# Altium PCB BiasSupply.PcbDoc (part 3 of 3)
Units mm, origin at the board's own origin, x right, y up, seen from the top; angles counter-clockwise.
Board outline 39 x 40.5 mm, 4 copper layers (Top Layer, Layer 2, Layer3, Bottom Layer), stack 0.661 mm thick; 168 components, 80 nets, 408 pads, 115 vias.
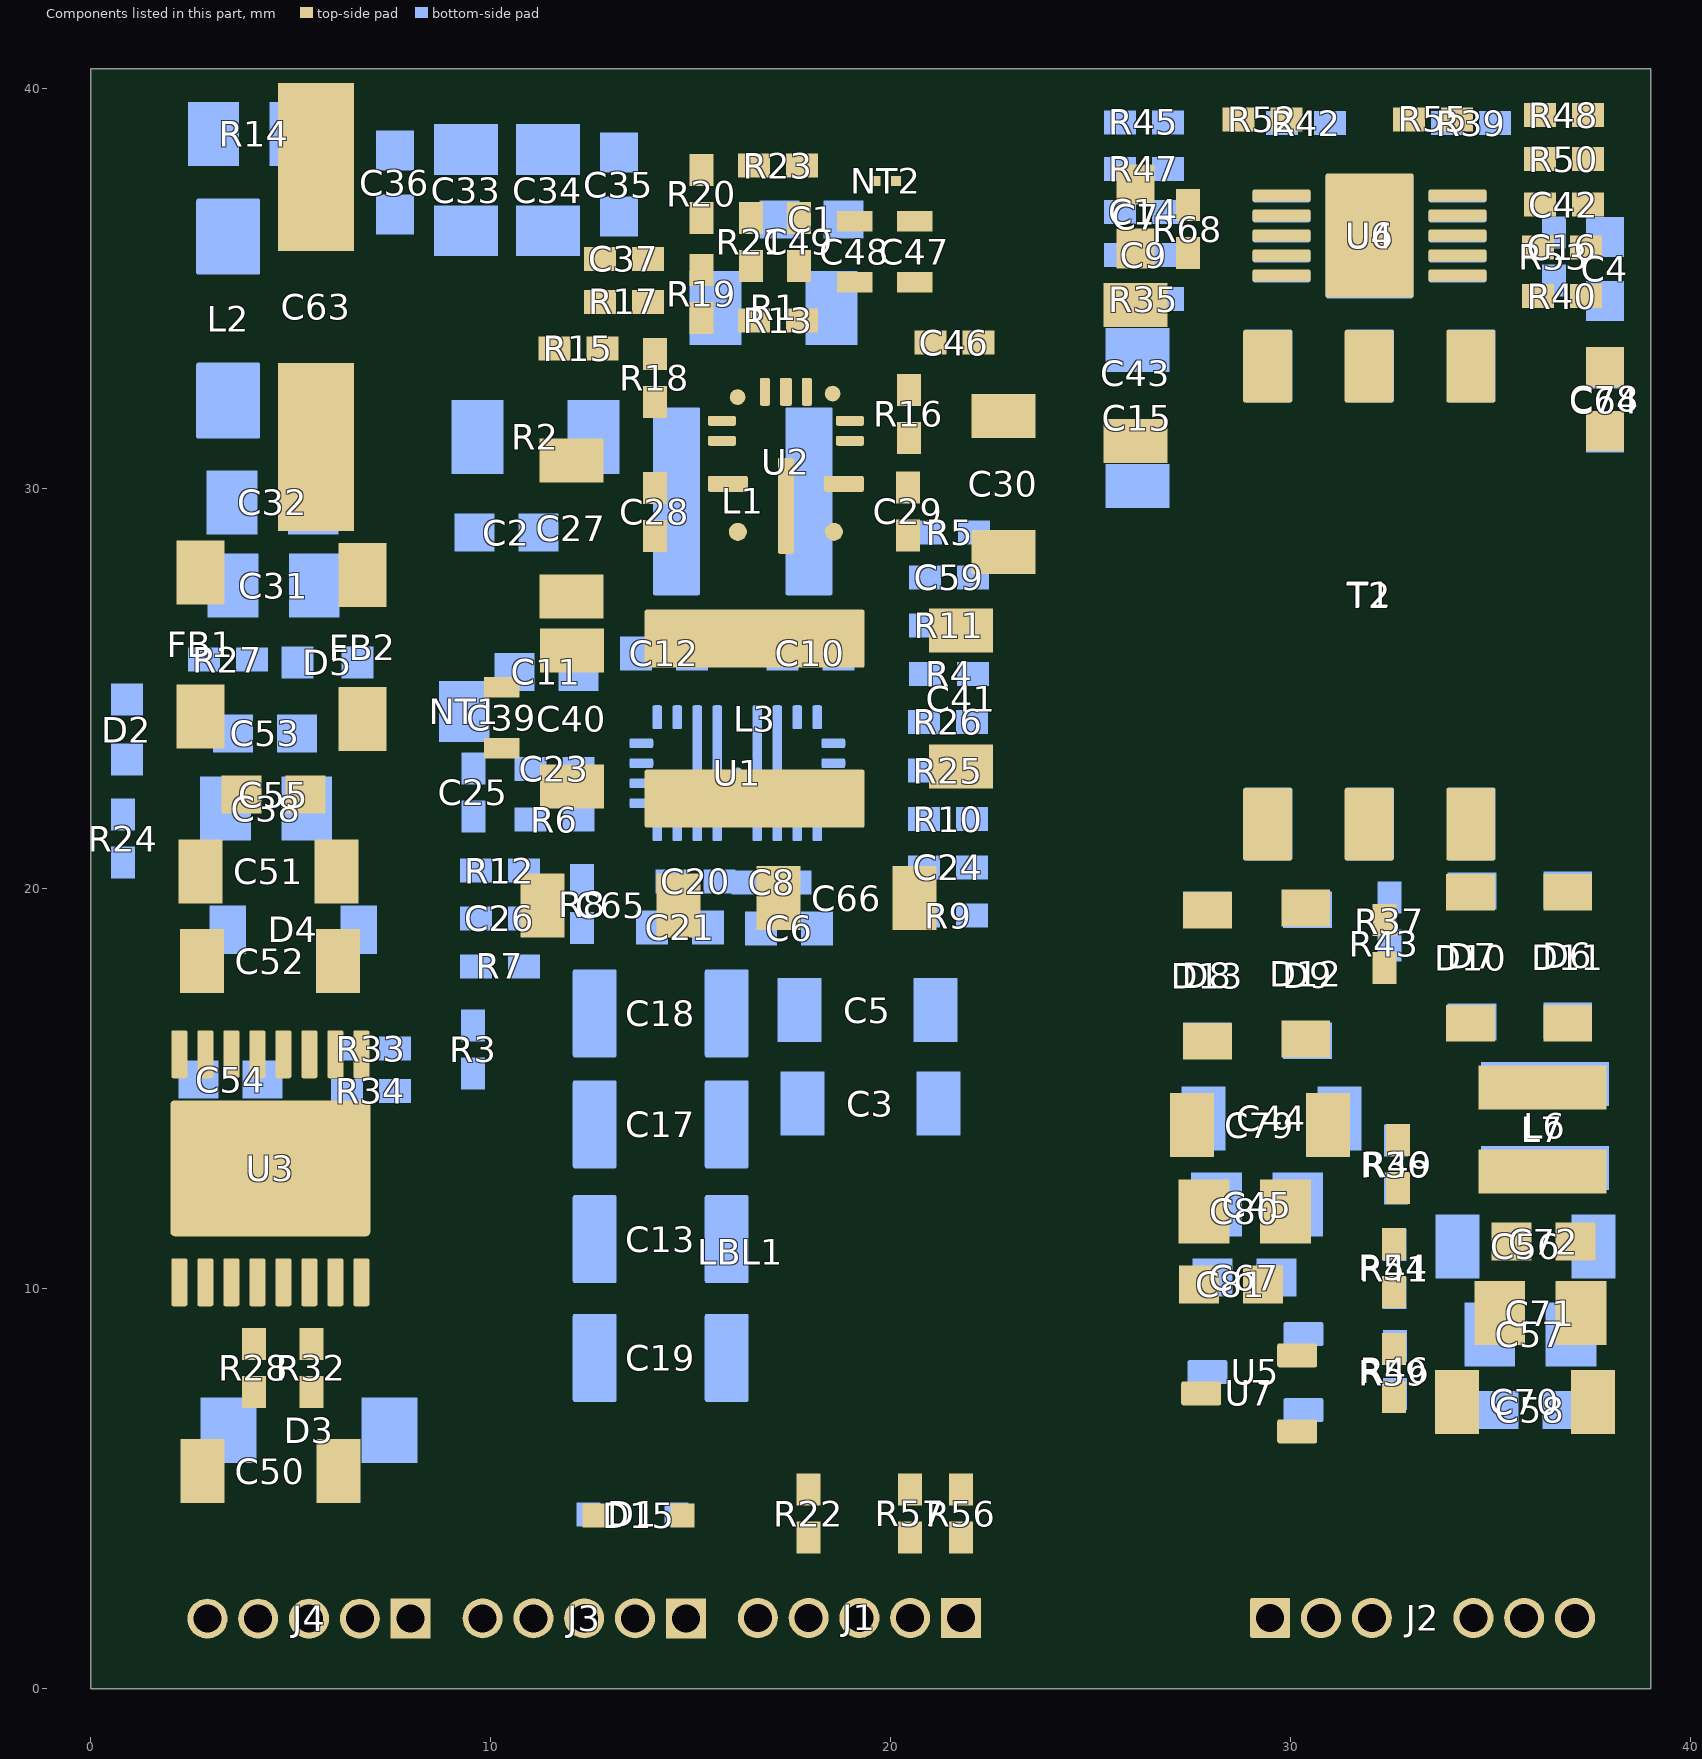
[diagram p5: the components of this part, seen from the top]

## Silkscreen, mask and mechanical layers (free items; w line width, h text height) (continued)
Drill Drawing:
  circle w0.254: c135.244,86.985 r0.333
  lines w0.254: 134.91,88.819 135.577,88.819 135.244,88.152 134.91,88.819 ; 134.91,89.819 135.077,89.819 135.244,89.652 135.41,89.819 135.577,89.819 135.41,89.985 135.577,90.152 135.41,90.152 135.244,90.319 135.077,90.152 134.91,90.152 135.077,89.985 134.91,89.819
  lines w0.305: 134.264,86.202 201.531,86.202 ; 134.264,90.702 201.531,90.702 ; 140.266,84.702 140.266,92.202 ; 147.137,84.702 147.137,92.202 ; 161.086,84.702 161.086,92.202 ; 166.637,84.702 166.637,92.202 ; 174.468,84.702 174.468,92.202 ; 189.772,84.702 189.772,92.202 ; 134.264,84.702 201.531,84.702 201.531,92.202 134.264,92.202 134.264,84.702
  text "Symbol" at 135.164,91.152 h0.72
  text "Quantity" at 140.716,91.152 h0.72
  text "Finished Hole Size" at 147.587,91.152 h0.72
  text "Plated" at 161.536,91.152 h0.72
  text "Hole Type" at 167.087,91.152 h0.72
  text "Drill Layer Pair" at 174.918,91.152 h0.72
  text "Hole Tolerance" at 190.222,91.152 h0.72
  text "69" at 140.716,89.652 h0.6
  text "8.00mil (0.203mm)" at 147.587,89.652 h0.6
  text "PTH" at 161.536,89.652 h0.6
  text "Round" at 167.087,89.652 h0.6
  text "Top Layer - Bottom Layer" at 174.918,89.652 h0.6
  text "46" at 140.716,88.152 h0.6
  text "11.81mil (0.300mm)" at 147.587,88.152 h0.6
  text "PTH" at 161.536,88.152 h0.6
  text "Round" at 167.087,88.152 h0.6
  text "Top Layer - Bottom Layer" at 174.918,88.152 h0.6
  text "21" at 140.716,86.652 h0.6
  text "27.56mil (0.700mm)" at 147.587,86.652 h0.6
  text "PTH" at 161.536,86.652 h0.6
  text "Round" at 167.087,86.652 h0.6
  text "Top Layer - Bottom Layer" at 174.918,86.652 h0.6
  text "136 Total" at 140.716,85.152 h0.6
  text ".Layer_Name" at 14.656,-21.806 h0.6
M17 Embedded Cavity:
  text ".Layer_Name" at 14.656,-21.806 h0.6
M18 Embedded Assembly:
  text ".Layer_Name" at 14.656,-21.806 h0.6
M19 Embedded Keepout:
  text ".Layer_Name" at 14.656,-21.806 h0.6

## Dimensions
0,0 to 39,0 on M2 Board Dimensions
0,-10.16 to 25.4,-10.16 on M2 Board Dimensions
